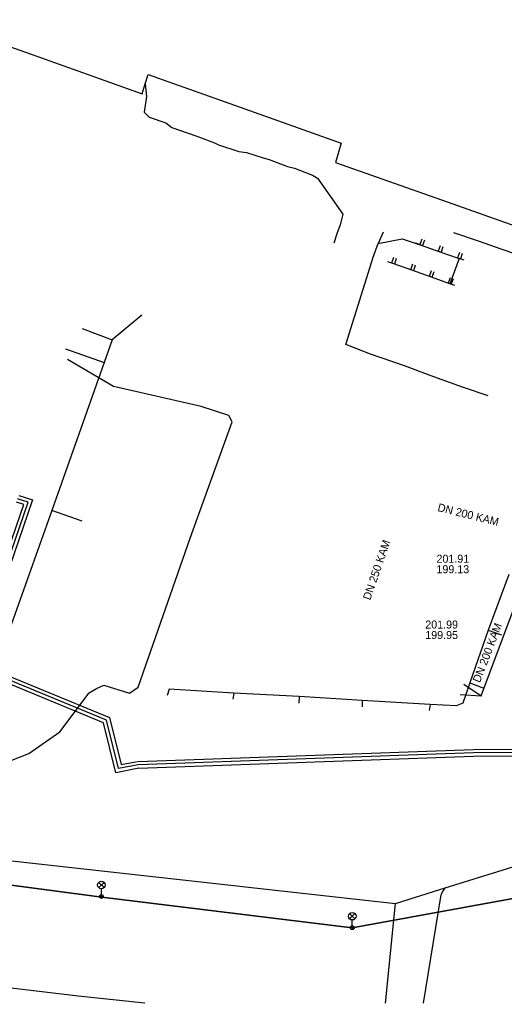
# Model space of a CAD drawing. Extents: x -598932 to -598196, y -1162210 to -1161504.
# Drawn here: x -598695.5 to -598647.1, y -1162207 to -1162108.6 of the extents above; entities that cross this region are included whole.
import ezdxf

# ---------------------------------------------------------------- set-up
doc = ezdxf.new("R2010")
doc.units = 0
for name, color, linetype in [('Vrstva 12', 7, 'Continuous'), ('Vrstva 19', 7, 'Continuous'), ('Vrstva 25', 7, 'Continuous'), ('Vrstva 26', 7, 'Continuous'), ('Vrstva 33', 7, 'Continuous'), ('Vrstva 55', 7, 'Continuous'), ('Vrstva 9', 7, 'Continuous')]:
    doc.layers.add(name, color=color, linetype=linetype)

msp = doc.modelspace()

# ---------------------------------------------------------------- linework, layer by layer
at = {"layer": 'Vrstva 19'}
msp.add_lwpolyline([(-598682.975, -1162206.96), (-598689.64, -1162206.25), (-598715.09, -1162203.22), (-598715.61, -1162203.12), (-598715.37, -1162200.99), (-598714.92, -1162198.4), (-598713.99, -1162192.37), (-598737.34, -1162189.37), (-598763.21, -1162186.18), (-598773.189, -1162184.991), (-598775.66, -1162184.73), (-598775.94, -1162184.75)], dxfattribs=at)
at = {"layer": 'Vrstva 25'}
for points in [[(-598683.649, -1162183.117), (-598685.624, -1162183.497), (-598686.83, -1162178.648), (-598700.25, -1162173.116), (-598694.648, -1162156.858), (-598695.706, -1162156.517)], [(-598635.714, -1162166.241), (-598635.92, -1162166.167), (-598636.647, -1162168.163), (-598637.21, -1162169.971), (-598641.849, -1162181.867), (-598650.127, -1162181.931), (-598683.649, -1162183.117)]]:
    msp.add_lwpolyline(points, dxfattribs=at)
at = {"layer": 'Vrstva 26'}
for points in [[(-598695.599, -1162156.184), (-598694.201, -1162156.634), (-598699.812, -1162172.918), (-598686.533, -1162178.392), (-598685.364, -1162183.091), (-598683.715, -1162182.773)], [(-598683.583, -1162183.461), (-598685.884, -1162183.903), (-598687.127, -1162178.904), (-598700.688, -1162173.314), (-598695.095, -1162157.082), (-598695.813, -1162156.85)], [(-598683.661, -1162182.767), (-598650.135, -1162181.581), (-598642.089, -1162181.519), (-598637.541, -1162169.855), (-598636.979, -1162168.051), (-598636.13, -1162165.72), (-598636.07, -1162165.741)], [(-598635.76, -1162166.75), (-598636.315, -1162168.275), (-598636.879, -1162170.087), (-598641.609, -1162182.215), (-598650.119, -1162182.281), (-598683.636, -1162183.467)]]:
    msp.add_lwpolyline(points, dxfattribs=at)
at = {"layer": 'Vrstva 33'}
for p, q in [((-598687.595, -1162194.865), (-598687.065, -1162195.395)), ((-598687.595, -1162195.395), (-598687.065, -1162194.865)), ((-598687.33, -1162196.28), (-598687.33, -1162195.505)), ((-598662.515, -1162197.985), (-598661.985, -1162198.515)), ((-598662.515, -1162198.515), (-598661.985, -1162197.985)), ((-598662.25, -1162199.4), (-598662.25, -1162198.625))]:
    msp.add_line(p, q, dxfattribs=at)
for centre, radius in [((-598687.33, -1162195.13), 0.375), ((-598687.33, -1162196.28), 0.19), ((-598687.33, -1162196.28), 0.05), ((-598662.25, -1162198.25), 0.375), ((-598662.25, -1162199.4), 0.19), ((-598662.25, -1162199.4), 0.05)]:
    msp.add_circle(centre, radius, dxfattribs=at)
at = {"layer": 'Vrstva 55'}
for p, q in [((-598659.16, -1162129.84), (-598659.65, -1162131)), ((-598655.37, -1162131.14), (-598655.887, -1162130.951)), ((-598655.313, -1162130.548), (-598655.511, -1162131.088)), ((-598655.032, -1162130.651), (-598655.229, -1162131.192)), ((-598653.51, -1162131.82), (-598654.03, -1162131.642)), ((-598653.466, -1162131.227), (-598653.652, -1162131.771)), ((-598653.182, -1162131.324), (-598653.368, -1162131.869)), ((-598651.536, -1162131.887), (-598651.722, -1162132.431)), ((-598651.252, -1162131.984), (-598651.438, -1162132.529)), ((-598658.18, -1162132.99), (-598658.698, -1162132.806)), ((-598658.129, -1162132.398), (-598658.321, -1162132.94)), ((-598657.847, -1162132.498), (-598658.039, -1162133.04)), ((-598656.229, -1162133.068), (-598656.421, -1162133.61)), ((-598651.06, -1162132.658), (-598651.58, -1162132.48)), ((-598655.947, -1162133.168), (-598656.139, -1162133.71)), ((-598654.379, -1162133.738), (-598654.571, -1162134.28)), ((-598654.097, -1162133.838), (-598654.289, -1162134.38)), ((-598652.459, -1162134.418), (-598652.651, -1162134.96)), ((-598651.992, -1162135.194), (-598652.51, -1162135.01)), ((-598652.177, -1162134.518), (-598652.369, -1162135.06)), ((-598683.64, -1162175.35), (-598678.46, -1162160.45)), ((-598646.6, -1162164.1), (-598648.66, -1162169.65)), ((-598648.66, -1162169.65), (-598650.49, -1162174.93)), ((-598648.66, -1162169.65), (-598647.34, -1162170.1)), ((-598674.1, -1162175.95), (-598674.18, -1162176.56)), ((-598667.57, -1162176.28), (-598674.1, -1162175.95)), ((-598667.57, -1162176.28), (-598667.58, -1162176.96)), ((-598661.25, -1162176.68), (-598667.57, -1162176.28)), ((-598661.25, -1162176.68), (-598661.27, -1162177.31)), ((-598654.48, -1162177.08), (-598661.25, -1162176.68)), ((-598654.48, -1162177.08), (-598654.56, -1162177.68))]:
    msp.add_line(p, q, dxfattribs=at)
for points in [[(-598704.08, -1162108.61), (-598693.9, -1162112.24), (-598683.26, -1162116.04), (-598682.95, -1162115.03)], [(-598682.95, -1162115.03), (-598682.67, -1162114.1), (-598672.98, -1162117.54), (-598663.35, -1162120.95), (-598663.94, -1162122.89), (-598653.33, -1162126.63), (-598643.27, -1162130.18)], [(-598682.95, -1162115.03), (-598682.83, -1162116.3), (-598683.06, -1162117.86), (-598682.56, -1162118.36), (-598680.9, -1162118.94), (-598680.28, -1162119.39), (-598678.64, -1162119.95), (-598677.79, -1162120.27), (-598676.01, -1162120.91), (-598675.63, -1162121.12), (-598673.58, -1162121.79), (-598672.83, -1162121.88), (-598671.15, -1162122.44), (-598670.57, -1162122.59), (-598668.71, -1162123.29), (-598668.01, -1162123.47), (-598666.22, -1162124.15), (-598665.72, -1162124.47), (-598663.18, -1162128.05), (-598663.47, -1162129.12), (-598663.81, -1162130.02), (-598664.11, -1162130.94)], [(-598652.14, -1162129.89), (-598649.68, -1162130.73), (-598647.29, -1162131.54), (-598644.88, -1162132.4), (-598642.4, -1162133.23), (-598640.01, -1162134.1)], [(-598648.66, -1162146.23), (-598651.22, -1162145.37), (-598654.45, -1162144.19), (-598657.02, -1162143.21), (-598660.43, -1162142.05), (-598662.9, -1162141.08), (-598660.13, -1162132.27), (-598659.65, -1162131)], [(-598659.65, -1162131), (-598657.25, -1162130.51), (-598655.37, -1162131.14), (-598653.51, -1162131.82), (-598651.58, -1162132.48), (-598652.51, -1162135.01), (-598654.43, -1162134.33), (-598656.28, -1162133.66), (-598658.18, -1162132.99)], [(-598678.46, -1162160.45), (-598674.26, -1162148.81), (-598674.59, -1162148.17), (-598677.35, -1162147.29), (-598686.13, -1162145.28), (-598690.73, -1162142.59)], [(-598737.62, -1162177.32), (-598724.34, -1162182), (-598723.57, -1162181.68), (-598722.12, -1162177.86), (-598721.35, -1162177.83), (-598716.35, -1162179.68), (-598716.07, -1162180.29), (-598714.92, -1162180.05), (-598706.03, -1162183.12), (-598702.36, -1162183.72), (-598698.5, -1162183.52), (-598694.6, -1162181.97), (-598691.49, -1162179.83), (-598688.54, -1162175.93), (-598687.82, -1162175.47), (-598687.08, -1162175.14), (-598684.53, -1162175.94), (-598683.64, -1162175.35)], [(-598650.49, -1162174.93), (-598651.2, -1162176.94), (-598651.85, -1162177.23), (-598654.48, -1162177.08)], [(-598650.49, -1162174.93), (-598649.36, -1162175.34), (-598649.15, -1162175.43)], [(-598674.1, -1162175.95), (-598680.55, -1162175.54), (-598680.77, -1162176.19)], [(-598734.15, -1162190.57), (-598723.421, -1162192.088), (-598710.96, -1162193.2), (-598687.278, -1162196.351), (-598662.25, -1162199.4), (-598645.273, -1162196.322), (-598639.12, -1162193.8), (-598645.273, -1162196.322), (-598662.25, -1162199.4), (-598687.278, -1162196.351), (-598710.96, -1162193.2)]]:
    msp.add_lwpolyline(points, dxfattribs=at)
at = {"layer": 'Vrstva 9'}
for p, q in [((-598683.284, -1162138.164), (-598686.24, -1162140.62)), ((-598689.25, -1162139.48), (-598686.24, -1162140.62)), ((-598690.931, -1162141.519), (-598687.047, -1162142.889)), ((-598689.26, -1162158.74), (-598692.301, -1162157.669)), ((-598649.37, -1162176.22), (-598645.73, -1162166.51)), ((-598651.087, -1162175.052), (-598649.37, -1162176.22)), ((-598651.448, -1162176.074), (-598649.37, -1162176.22)), ((-598652.978, -1162195.422), (-598640.45, -1162191.51)), ((-598657.924, -1162196.995), (-598652.977, -1162195.422)), ((-598658.933, -1162206.96), (-598657.924, -1162196.995))]:
    msp.add_line(p, q, dxfattribs=at)
for points in [[(-598686.24, -1162140.62), (-598687.047, -1162142.889), (-598692.301, -1162157.669), (-598699.699, -1162178.482), (-598700.8, -1162181.58)], [(-598725.49, -1162189.45), (-598724.197, -1162189.589), (-598723.999, -1162189.61), (-598722.677, -1162189.762), (-598721.915, -1162189.849), (-598721.674, -1162189.876), (-598719.388, -1162190.131), (-598657.924, -1162196.995)], [(-598655.143, -1162206.96), (-598653.412, -1162196.328), (-598653.318, -1162196.007), (-598653.186, -1162195.781), (-598652.977, -1162195.422)]]:
    msp.add_lwpolyline(points, dxfattribs=at)

# ---------------------------------------------------------------- texts
at = {"layer": 'Vrstva 12'}
for s, rotation, p in [('DN 200 KAM', 346, (-598653.776, -1162157.724)), ('DN 250 KAM', 71, (-598660.457, -1162166.701)), ('DN 200 KAM', 69, (-598649.492, -1162174.96))]:
    msp.add_text(s, height=0.8, rotation=rotation, dxfattribs=at).set_placement(p)
for s, p in [('201.91', (-598653.834, -1162162.906)), ('199.13', (-598653.834, -1162163.956)), ('201.99', (-598654.953, -1162169.485)), ('199.95', (-598654.953, -1162170.535))]:
    msp.add_text(s, height=0.8, dxfattribs=at).set_placement(p)

doc.saveas('drawing.dxf')
